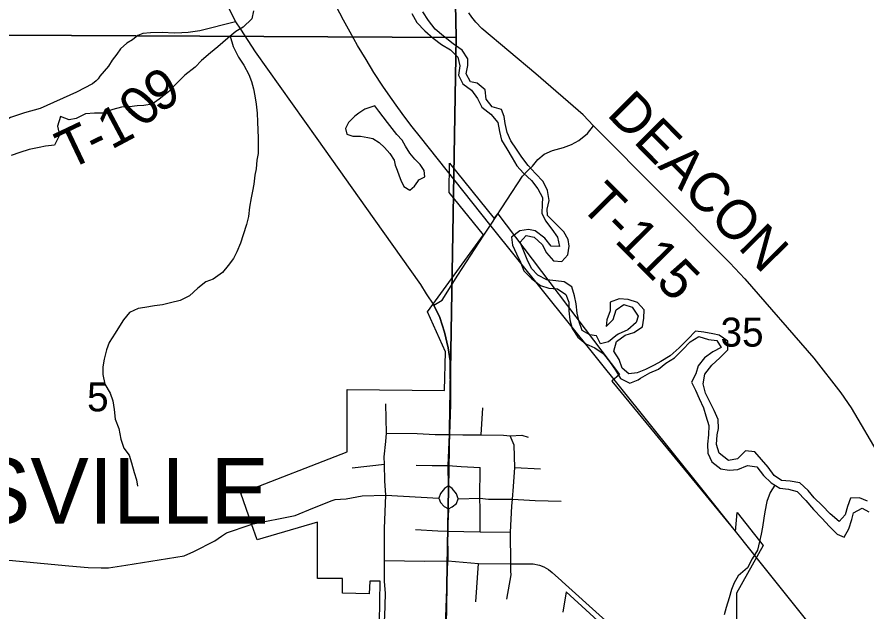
# Model space of a CAD drawing. Extents: x -7.1 to 34, y 0 to 22.
# Drawn here: x 3.24 to 4.468, y 18.905 to 19.764 of the extents above; entities that cross this region are included whole.
import ezdxf

# ---------------------------------------------------------------- set-up
doc = ezdxf.new("R2010")
doc.units = 0
for name, color, linetype in [('GM_X_City_Street', 7, 'Continuous'), ('GM_X_Corporation', 7, 'Continuous'), ('GM_X_Corporation_Text', 7, 'Continuous'), ('GM_X_County_Road', 7, 'Continuous'), ('GM_X_Major_River', 7, 'Continuous'), ('GM_X_Minor_Lake', 7, 'Continuous'), ('GM_X_Minor_River', 7, 'Continuous'), ('GM_X_Rail_Line', 7, 'Continuous'), ('GM_X_Section', 7, 'Continuous'), ('GM_X_Section_Text', 7, 'Continuous'), ('GM_X_State_Route', 7, 'Continuous'), ('GM_X_Township_Road', 7, 'Continuous'), ('GM_X_Township_Road_Text', 7, 'Continuous')]:
    doc.layers.add(name, color=color, linetype=linetype)

msp = doc.modelspace()

# ---------------------------------------------------------------- linework, layer by layer
at = {"layer": 'GM_X_City_Street'}
for p, q in [((3.9111, 19.1601), (3.9133, 19.199)), ((3.7245, 19.1123), (3.7713, 19.1173)), ((3.9597, 19.1128), (3.9969, 19.1109)), ((3.9035, 18.9185), (3.9071, 18.9739))]:
    msp.add_line(p, q, dxfattribs=at)
for points in [[(3.7732, 19.1501), (3.7744, 19.1623), (3.773, 19.2045)], [(3.7744, 19.1623), (3.8185, 19.162), (3.8444, 19.1604), (3.8653, 19.1602), (3.8844, 19.1598), (3.9111, 19.1601), (3.9436, 19.1592), (3.9533, 19.1584), (3.97, 19.1592), (3.9791, 19.1567)], [(3.9542, 18.963), (3.954, 18.9736), (3.9537, 19.0194), (3.9555, 19.0567), (3.9566, 19.067), (3.958, 19.0853), (3.9597, 19.1128), (3.9589, 19.1451), (3.9533, 19.1584)], [(3.7682, 18.8577), (3.7719, 18.8975), (3.7726, 18.9304), (3.7714, 18.9485), (3.7712, 18.9783), (3.7712, 19.0245), (3.7731, 19.0726), (3.7716, 19.0936), (3.7713, 19.1173), (3.771, 19.1279), (3.7732, 19.1501)], [(3.817, 19.1159), (3.8403, 19.1157), (3.8633, 19.1154), (3.8824, 19.1139), (3.9097, 19.1128)], [(3.9096, 19.0199), (3.9099, 19.0529), (3.9091, 19.0681), (3.9097, 19.1128)], [(3.8778, 19.0672), (3.9091, 19.0681), (3.9219, 19.067), (3.9566, 19.067), (3.9891, 19.0651), (4.0269, 19.0642)], [(3.8162, 19.0229), (3.8486, 19.021), (3.8625, 19.0205), (3.9096, 19.0199), (3.9537, 19.0194)], [(3.7712, 18.9783), (3.8293, 18.9773), (3.8627, 18.9778)], [(3.8586, 18.8255), (3.8593, 18.883), (3.8627, 18.9778)], [(3.9483, 18.9223), (3.9543, 18.9577), (3.9542, 18.963)]]:
    msp.add_lwpolyline(points, dxfattribs=at)
at = {"layer": 'GM_X_Corporation'}
for points in [[(3.7629, 18.8287), (3.7648, 18.9482), (3.75, 18.9483), (3.7489, 18.9302), (3.7107, 18.9312), (3.7104, 18.9522), (3.6745, 18.9524), (3.6745, 19.0337), (3.5871, 19.008), (3.5787, 19.0312), (3.5633, 19.0755), (3.7173, 19.1352), (3.7173, 19.2252), (3.858, 19.224), (3.8593, 19.2799), (3.8336, 19.3377), (3.9147, 19.4489), (3.8646, 19.51), (3.8655, 19.5525), (3.93, 19.4725), (3.9353, 19.4793), (4.111, 19.2469), (4.1, 19.2373), (4.2789, 19.0201), (4.2812, 19.0478), (4.3191, 19.0001), (4.2804, 18.9312), (4.2802, 18.8154)], [(4.1594, 18.8181), (4.0339, 18.9328), (4.0293, 18.9035)]]:
    msp.add_lwpolyline(points, dxfattribs=at)
at = {"layer": 'GM_X_County_Road'}
for p, q in [((3.8633, 19.1154), (3.8653, 19.1602)), ((3.8638, 19.0861), (3.8633, 19.1154))]:
    msp.add_line(p, q, dxfattribs=at)
for points in [[(3.9255, 19.4645), (3.9708, 19.5338), (3.9785, 19.5422), (3.9854, 19.5484), (3.9894, 19.5531), (3.9929, 19.5581), (4.0021, 19.5658), (4.0142, 19.5708), (4.0301, 19.5753), (4.0418, 19.5794), (4.0526, 19.5851), (4.0647, 19.5953), (4.0736, 19.6067), (4.0586, 19.6224), (3.9902, 19.6816), (3.9121, 19.7473), (3.9035, 19.7562), (3.8977, 19.7634), (3.8935, 19.7701)], [(3.8425, 19.3473), (3.8548, 19.3544), (3.8773, 19.3907), (3.9149, 19.4484), (3.9255, 19.4645)], [(3.8666, 19.2133), (3.8664, 19.2666), (3.8636, 19.2855), (3.8581, 19.3081), (3.8515, 19.3295), (3.8425, 19.3473)], [(3.8653, 19.1602), (3.8666, 19.2037), (3.8666, 19.2133)], [(3.8778, 19.0672), (3.8756, 19.0745), (3.8693, 19.0824), (3.8638, 19.0861)], [(3.577, 19.03), (3.5789, 19.0306), (3.6421, 19.0435), (3.6678, 19.0539), (3.6955, 19.0651), (3.7001, 19.0662), (3.7076, 19.0669), (3.7157, 19.0672), (3.7388, 19.0717), (3.7731, 19.0726), (3.85, 19.0685)], [(3.85, 19.0685), (3.8524, 19.0622), (3.8577, 19.0565), (3.8639, 19.0531)], [(3.8639, 19.0531), (3.8691, 19.0556), (3.8752, 19.0604), (3.8778, 19.0672)], [(3.2073, 18.9808), (3.3146, 18.9707), (3.3425, 18.9682), (3.3615, 18.9677), (3.3722, 18.9676), (3.397, 18.9715), (3.4816, 18.9851), (3.4954, 18.991), (3.5258, 19.0065), (3.5356, 19.0135), (3.5428, 19.0182), (3.577, 19.03)]]:
    msp.add_lwpolyline(points, dxfattribs=at)
at = {"layer": 'GM_X_Major_River'}
for points in [[(3.9933, 19.3907), (3.984, 19.4004), (3.9777, 19.4132), (3.9726, 19.4256), (3.9674, 19.4385), (3.976, 19.4481), (3.9878, 19.4456), (3.9994, 19.4348), (4.0057, 19.4228), (4.0158, 19.4116), (4.028, 19.4102), (4.0365, 19.4202), (4.0386, 19.4324), (4.0369, 19.4423), (4.0307, 19.4535), (4.0198, 19.4644), (4.0071, 19.4767), (4.0065, 19.4862), (4.0094, 19.4987), (4.0072, 19.5131), (4.0009, 19.5259), (3.9897, 19.5375), (3.9789, 19.5491), (3.97, 19.5611), (3.9622, 19.5727), (3.954, 19.5847), (3.9488, 19.5971), (3.9456, 19.61), (3.9443, 19.6202), (3.9403, 19.63), (3.9269, 19.6339), (3.9184, 19.6452), (3.917, 19.6584), (3.9054, 19.6681), (3.8959, 19.6699), (3.8896, 19.6815), (3.8917, 19.6937), (3.8916, 19.7035), (3.8834, 19.7159), (3.8707, 19.7252), (3.8564, 19.7363), (3.8445, 19.7464), (3.8348, 19.7588), (3.8269, 19.7711)], [(3.8106, 19.769), (3.8181, 19.7558), (3.8297, 19.7439), (3.8416, 19.7334), (3.8536, 19.7242), (3.8666, 19.7164), (3.8774, 19.706), (3.8803, 19.6931), (3.8783, 19.6798), (3.8846, 19.667), (3.8973, 19.6581), (3.9058, 19.6461), (3.9121, 19.6337), (3.9252, 19.6233), (3.9353, 19.6113), (3.9374, 19.5981), (3.9407, 19.5856), (3.9481, 19.5732), (3.9559, 19.5604), (3.9626, 19.5488), (3.9722, 19.5379), (3.9838, 19.5275), (3.9931, 19.5155), (3.9998, 19.5027), (3.9992, 19.4929), (3.9987, 19.4803), (4.0042, 19.469), (4.0135, 19.4574), (4.0213, 19.4458), (4.0246, 19.4322), (4.0124, 19.4324), (4.0031, 19.444), (3.9892, 19.4548), (3.9797, 19.4565), (3.9668, 19.4548), (3.9551, 19.4458), (3.9565, 19.4341), (3.9624, 19.4213), (3.9679, 19.4096), (3.9727, 19.3968), (3.9843, 19.3852), (3.997, 19.3756), (4.0088, 19.372), (4.0214, 19.371), (4.0337, 19.3629), (4.0377, 19.3516), (4.0379, 19.3391), (4.0392, 19.3262), (4.0425, 19.3137), (4.0507, 19.301), (4.0626, 19.2913), (4.0756, 19.2854), (4.0876, 19.2773), (4.0969, 19.2661), (4.1054, 19.2533), (4.1125, 19.2413), (4.1259, 19.2347), (4.1384, 19.2394)], [(4.1061, 19.303), (4.0953, 19.2941), (4.0839, 19.2916), (4.078, 19.3029), (4.0681, 19.3043), (4.057, 19.3109), (4.053, 19.3234), (4.0501, 19.3359), (4.0484, 19.3491), (4.0463, 19.3608), (4.0423, 19.3737), (4.0311, 19.3811), (4.0193, 19.3824), (4.006, 19.3837), (3.9933, 19.3907)], [(4.4701, 19.0639), (4.4582, 19.069), (4.4453, 19.0684), (4.4409, 19.0562), (4.4377, 19.0444), (4.4287, 19.0347), (4.416, 19.0459), (4.4044, 19.0579), (4.3928, 19.0687), (4.3839, 19.0795), (4.3719, 19.0907), (4.3582, 19.0928), (4.3453, 19.0937), (4.3349, 19.1011), (4.326, 19.1131), (4.3166, 19.1243), (4.307, 19.1352), (4.2933, 19.1369), (4.2817, 19.1253), (4.2688, 19.1228), (4.2553, 19.1336), (4.2513, 19.146), (4.2526, 19.1597), (4.2543, 19.1692), (4.2537, 19.1821), (4.2482, 19.1949), (4.2419, 19.2074), (4.2356, 19.2202), (4.2323, 19.2338), (4.2348, 19.2475), (4.2448, 19.2605), (4.2561, 19.271), (4.2677, 19.2825), (4.2678, 19.2954), (4.2555, 19.304), (4.246, 19.3061), (4.233, 19.3081), (4.2212, 19.3098), (4.21, 19.2983), (4.1973, 19.2855), (4.1845, 19.2743), (4.171, 19.2661), (4.1612, 19.2607), (4.1488, 19.2544), (4.1367, 19.2496), (4.1249, 19.2479), (4.1149, 19.2561), (4.1109, 19.2689), (4.1031, 19.281), (4.1067, 19.2947), (4.1194, 19.304), (4.1319, 19.308), (4.1447, 19.3158), (4.1464, 19.3283), (4.147, 19.3405), (4.1373, 19.351), (4.1235, 19.3553), (4.1106, 19.3566), (4.0977, 19.3518), (4.0976, 19.3389), (4.0928, 19.3263), (4.0919, 19.3164), (4.1019, 19.3268), (4.1063, 19.3406), (4.1176, 19.3484), (4.1294, 19.3444), (4.138, 19.3316), (4.1351, 19.3221), (4.1231, 19.3116), (4.1095, 19.3053), (4.1061, 19.303)], [(4.1384, 19.2394), (4.1417, 19.2417), (4.1553, 19.2496), (4.1674, 19.2547), (4.1783, 19.2636), (4.1907, 19.2714), (4.2023, 19.2826), (4.2135, 19.2942), (4.2259, 19.302), (4.2397, 19.2976), (4.2518, 19.2963), (4.2581, 19.2862), (4.2464, 19.2799), (4.234, 19.2714), (4.2251, 19.2598), (4.2218, 19.248), (4.2152, 19.2358), (4.2211, 19.2245), (4.2262, 19.2124), (4.2325, 19.1989), (4.2362, 19.1871), (4.2406, 19.1736), (4.24, 19.1599), (4.2384, 19.1462), (4.239, 19.1333), (4.2449, 19.1209), (4.2576, 19.1105), (4.2698, 19.1088), (4.2823, 19.1097), (4.2963, 19.1157), (4.31, 19.1136), (4.3193, 19.1009), (4.3305, 19.0904), (4.3432, 19.0827), (4.3554, 19.0813), (4.3683, 19.0781), (4.3807, 19.0651), (4.392, 19.052), (4.404, 19.0393), (4.4148, 19.0273), (4.426, 19.0165), (4.436, 19.0121), (4.443, 19.024), (4.4473, 19.0373), (4.4498, 19.0472), (4.4623, 19.0539), (4.4718, 19.0484)]]:
    msp.add_lwpolyline(points, dxfattribs=at)
at = {"layer": 'GM_X_Minor_Lake'}
for points in [[(3.7573, 19.6353), (3.7429, 19.6306), (3.7342, 19.6248), (3.7282, 19.6206), (3.7191, 19.6114), (3.715, 19.6026), (3.7166, 19.5943), (3.7257, 19.5917), (3.7368, 19.5918), (3.747, 19.5896), (3.7546, 19.5882), (3.7634, 19.5822), (3.7711, 19.5754), (3.7788, 19.5664), (3.7853, 19.557), (3.7869, 19.5498), (3.7896, 19.5426), (3.7923, 19.5342), (3.7947, 19.5278), (3.7993, 19.5188), (3.8081, 19.5135), (3.8149, 19.5193), (3.8194, 19.5262)], [(3.8194, 19.5262), (3.8209, 19.5284), (3.8296, 19.533), (3.8287, 19.5421), (3.823, 19.5504), (3.8153, 19.5583), (3.808, 19.567), (3.8018, 19.5772), (3.7968, 19.5859), (3.7892, 19.5938), (3.7826, 19.6028), (3.7757, 19.6115), (3.7692, 19.6194), (3.763, 19.6277), (3.7573, 19.6353)]]:
    msp.add_lwpolyline(points, dxfattribs=at)
at = {"layer": 'GM_X_Minor_River'}
for points in [[(3.5817, 19.7726), (3.5795, 19.7612), (3.5671, 19.7493), (3.5565, 19.7428), (3.5448, 19.7332), (3.5301, 19.7206), (3.5196, 19.7121), (3.5068, 19.701), (3.4977, 19.6911), (3.4827, 19.6796), (3.4698, 19.6673), (3.4589, 19.6558), (3.4454, 19.6451), (3.4355, 19.6378), (3.4234, 19.6358), (3.4135, 19.6353), (3.4025, 19.6341), (3.3908, 19.6333), (3.3783, 19.6301), (3.3635, 19.625), (3.3521, 19.6246), (3.3388, 19.6241), (3.3252, 19.6171), (3.3153, 19.6151), (3.3028, 19.62), (3.2983, 19.6059), (3.3011, 19.593), (3.294, 19.5785), (3.2811, 19.5769), (3.2716, 19.5753), (3.2576, 19.5722), (3.244, 19.5682), (3.2311, 19.5636)], [(3.5481, 19.7359), (3.5526, 19.7211), (3.5599, 19.7057), (3.568, 19.694), (3.5749, 19.6807), (3.5788, 19.6705), (3.5816, 19.6599), (3.5839, 19.6501), (3.5859, 19.638), (3.5872, 19.6247), (3.5877, 19.6122), (3.5882, 19.6004), (3.5887, 19.5894), (3.5888, 19.5773), (3.5885, 19.5667), (3.5867, 19.5568), (3.5856, 19.5446), (3.5838, 19.5351), (3.5824, 19.5222), (3.5802, 19.5123), (3.5784, 19.5024), (3.5762, 19.4888), (3.5748, 19.4755), (3.5715, 19.4637), (3.5667, 19.4492), (3.563, 19.437), (3.5578, 19.4245), (3.553, 19.415), (3.5451, 19.4046), (3.5368, 19.3947), (3.5236, 19.3851), (3.513, 19.3808), (3.5013, 19.372), (3.4892, 19.3609), (3.4756, 19.354), (3.462, 19.3508), (3.4502, 19.348), (3.4385, 19.3464), (3.4248, 19.3437), (3.415, 19.3424), (3.4025, 19.3366), (3.3938, 19.3263), (3.3882, 19.3168), (3.3818, 19.3069), (3.3732, 19.2935), (3.3691, 19.2825), (3.3658, 19.2692), (3.364, 19.2581), (3.3638, 19.2471), (3.3669, 19.2331), (3.3746, 19.2199), (3.3785, 19.2089), (3.3805, 19.1964), (3.3818, 19.1824), (3.3872, 19.1688), (3.39, 19.1536), (3.3943, 19.1404), (3.402, 19.1306), (3.4055, 19.1192), (3.4094, 19.1056), (3.4125, 19.095), (3.4142, 19.0855)], [(4.3357, 19.0872), (4.3292, 19.0766), (4.3244, 19.0637), (4.3215, 19.0488), (4.32, 19.0393), (4.3179, 19.0264), (4.3161, 19.0162), (4.3135, 19.0059), (4.3106, 18.993), (4.3031, 18.9804), (4.2963, 18.9674), (4.2828, 18.9559), (4.2772, 18.946), (4.2731, 18.9361), (4.2697, 18.9243), (4.2653, 18.9102), (4.2627, 18.8999)]]:
    msp.add_lwpolyline(points, dxfattribs=at)
at = {"layer": 'GM_X_Rail_Line'}
msp.add_lwpolyline([(4.5624, 18.6665), (4.4492, 18.8079), (4.3168, 18.9733), (4.2285, 19.0844), (3.9238, 19.4641), (3.8232, 19.5901), (3.8111, 19.6051), (3.8009, 19.6191), (3.7907, 19.6328), (3.78, 19.6478), (3.7691, 19.6638), (3.7561, 19.6836), (3.7446, 19.7022), (3.7324, 19.7226), (3.7215, 19.7419), (3.7118, 19.7593), (3.7016, 19.7793)], dxfattribs=at)
at = {"layer": 'GM_X_Section'}
for points in [[(3.8931, 20.7247), (3.8731, 19.8315), (3.8749, 19.7341), (2.8549, 19.7393), (2.8771, 20.7376)], [(3.8731, 19.8315), (4.7229, 19.8074), (4.6987, 18.8125), (3.8597, 18.828), (3.8749, 19.7341)], [(2.8549, 19.7393), (3.8749, 19.7341), (3.8597, 18.828), (3.8583, 18.7127), (2.8366, 18.7324)]]:
    msp.add_lwpolyline(points, close=True, dxfattribs=at)
at = {"layer": 'GM_X_State_Route'}
for p, q in [((3.8318, 19.3639), (3.8425, 19.3473)), ((3.8653, 19.1602), (3.8633, 19.1154)), ((3.8633, 19.1154), (3.8638, 19.0861))]:
    msp.add_line(p, q, dxfattribs=at)
for points in [[(3.5227, 19.8255), (3.5558, 19.7569), (3.5629, 19.7464), (3.5841, 19.7135), (3.6734, 19.5881), (3.7561, 19.4719), (3.8233, 19.3771), (3.8318, 19.3639)], [(3.8425, 19.3473), (3.8515, 19.3295), (3.8581, 19.3081), (3.8636, 19.2855), (3.8664, 19.2666), (3.8666, 19.2133)], [(3.8666, 19.2133), (3.8666, 19.2037), (3.8653, 19.1602)], [(3.8638, 19.0861), (3.8579, 19.0821), (3.8522, 19.0753), (3.85, 19.0685)], [(3.8778, 19.0672), (3.8756, 19.0745), (3.8693, 19.0824), (3.8638, 19.0861)], [(3.85, 19.0685), (3.8524, 19.0622), (3.8577, 19.0565), (3.8639, 19.0531)], [(3.8639, 19.0531), (3.8691, 19.0556), (3.8752, 19.0604), (3.8778, 19.0672)], [(3.8639, 19.0531), (3.8625, 19.0205), (3.8627, 18.9778), (3.9071, 18.9739), (3.954, 18.9736), (3.9865, 18.9732), (3.9956, 18.9717), (4.0019, 18.9689), (4.0086, 18.9654), (4.0137, 18.9608), (4.0275, 18.9486)], [(4.0275, 18.9486), (4.0283, 18.9479), (4.0867, 18.8952), (4.1653, 18.8259)]]:
    msp.add_lwpolyline(points, dxfattribs=at)
at = {"layer": 'GM_X_Township_Road'}
for points in [[(3.5558, 19.7569), (3.504, 19.7438), (3.4872, 19.7415), (3.478, 19.7411)], [(3.478, 19.7411), (3.4677, 19.7405), (3.4499, 19.7412), (3.4327, 19.7409), (3.4218, 19.7399), (3.4145, 19.7372), (3.4066, 19.7309), (3.3985, 19.7259), (3.3893, 19.718), (3.3841, 19.7101), (3.3775, 19.7016), (3.3719, 19.6926), (3.3595, 19.6782), (3.3571, 19.6743), (3.3544, 19.6714), (3.3489, 19.6673), (3.3257, 19.6553), (3.2732, 19.6316), (3.2504, 19.6251), (3.2304, 19.6186), (3.2191, 19.6117), (3.2154, 19.6102), (3.1942, 19.6014), (3.0953, 19.5347)], [(4.0736, 19.6067), (4.2707, 19.4084), (4.2926, 19.3852), (4.3921, 19.2706), (4.4311, 19.2208), (4.4465, 19.1989), (4.488, 19.1277)]]:
    msp.add_lwpolyline(points, dxfattribs=at)

# ---------------------------------------------------------------- texts
at = {"layer": 'GM_X_Corporation_Text'}
msp.add_text('LEESVILLE', height=0.0947, rotation=0, dxfattribs=at).set_placement((2.9353, 19.0317))
at = {"layer": 'GM_X_Section_Text'}
for s, height, p in [('35', 0.04186, (4.2573, 19.2874)), ('5', 0.0419, (3.3411, 19.1938))]:
    msp.add_text(s, height=height, rotation=0, dxfattribs=at).set_placement(p)
at = {"layer": 'GM_X_Township_Road_Text'}
for s, height, rotation, p in [('9', 0.0568, 27.9034, (3.4432, 19.6243)), ('0', 0.0568, 48.1531, (3.4241, 19.6014)), ('DEACON', 0.05682, 314.6496, (4.0912, 19.6223)), ('1', 0.0568, 28.0076, (3.3761, 19.5716)), ('T', 0.0568, 25.4083, (3.3142, 19.542)), ('-', 0.0568, 25.6389, (3.3528, 19.5604)), ('T-115', 0.05682, 314.8019, (4.052, 19.4904))]:
    msp.add_text(s, height=height, rotation=rotation, dxfattribs=at).set_placement(p)

doc.saveas('drawing.dxf')
